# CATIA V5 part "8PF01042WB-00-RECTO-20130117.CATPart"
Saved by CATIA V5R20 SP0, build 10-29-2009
Part number: 8PF01042WB-00-RECTO-20130117
Revision: ANY
Definition: UNKNOWN
Nomenclature: 8PF01042WB-00-RECTO-20130117
Source: Unknown
Bounding box of the stored display mesh (mm): x 1681.949 to 1881.949, y 1407.509 to 1411.509, z 0 to 10
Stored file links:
  C:\Users\Utente\Desktop\IO LAVORO\3D X SITO CF\CUMSA\3D files PF\PF 1042WB\8PF01042WB-00-RECTO-20130117.CATPart
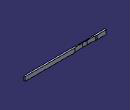
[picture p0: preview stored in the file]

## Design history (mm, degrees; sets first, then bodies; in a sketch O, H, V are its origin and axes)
Body1 "Cortar-Extruir1" (main body)
  Solid1: solid without history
